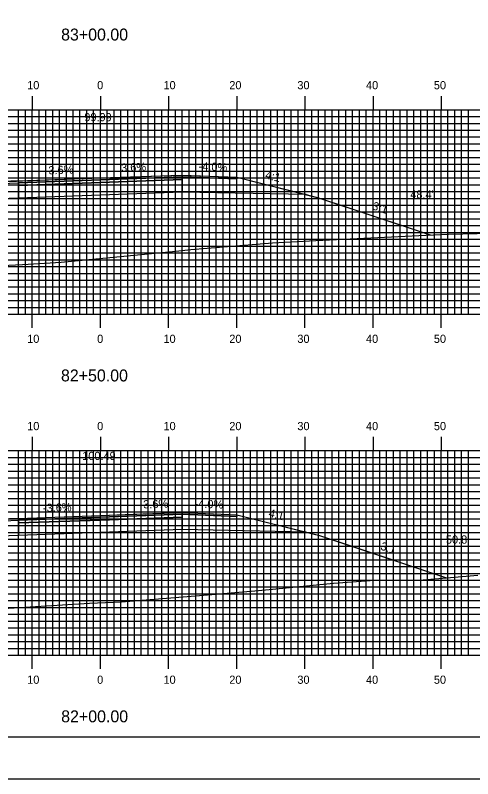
# Model space of a CAD drawing. Extents: x 1762972 to 1763315, y 442591 to 442811.
# Drawn here: x 1763124.8 to 1763191.9, y 442590.5 to 442702.5 of the extents above; entities that cross this region are included whole.
import ezdxf

# ---------------------------------------------------------------- set-up
doc = ezdxf.new("R2010")
doc.units = 0
for name, color, linetype in [('ANNOTATION', 7, 'Continuous'), ('BORDER', 7, 'Continuous'), ('D_Roadway_Centerline', 7, 'Continuous'), ('D_Roadway_Centerline_Text', 7, 'Continuous'), ('D_Roadway_Edge_Shoulder', 7, 'Continuous'), ('D_Roadway_Edge_TW', 7, 'Continuous'), ('D_Roadway_Pavement', 7, 'Continuous'), ('D_Roadway_SlopeLines', 7, 'Continuous'), ('D_Roadway_SubGrade', 7, 'Continuous'), ('D_Text_Standard', 7, 'Continuous'), ('H_V ANNOTATION', 7, 'Continuous'), ('MAJOR', 7, 'Continuous'), ('MINOR', 7, 'Continuous'), ('PLOT BOUNDARY', 7, 'Continuous'), ('S_Roadway_Centerline', 7, 'Continuous')]:
    doc.layers.add(name, color=color, linetype=linetype)

msp = doc.modelspace()

# ---------------------------------------------------------------- linework, layer by layer
at = {"layer": 'BORDER'}
msp.add_lwpolyline([(1762987.69, 442596.67), (1763307.69, 442596.67), (1763307.69, 442806.67), (1762987.69, 442806.67)], close=True, dxfattribs=at)
at = {"layer": 'D_Roadway_Centerline'}
for points in [[(1763079.48, 442666.3), (1763079.48, 442666.3), (1763105.29, 442674.9), (1763105.76, 442675.02), (1763117.29, 442677.9), (1763117.29, 442677.9), (1763117.3, 442677.9), (1763124.95, 442678.21), (1763125.29, 442678.22), (1763125.84, 442678.24), (1763137.29, 442678.66), (1763147.6, 442679.03), (1763149.29, 442679.09), (1763150.49, 442679.04), (1763157.29, 442678.77), (1763157.29, 442678.77), (1763166.47, 442676.47), (1763167.47, 442676.22), (1763169.29, 442675.77), (1763173.61, 442674.33), (1763185.68, 442670.3)], [(1763077.39, 442616.1), (1763105.29, 442625.4), (1763105.29, 442625.4), (1763105.4, 442625.43), (1763105.76, 442625.52), (1763105.76, 442625.52), (1763110.16, 442626.62), (1763117.29, 442628.4), (1763117.29, 442628.4), (1763125.29, 442628.72), (1763137.29, 442629.16), (1763137.29, 442629.16), (1763142.07, 442629.33), (1763149.29, 442629.59), (1763149.3, 442629.59), (1763157.29, 442629.27), (1763167.47, 442626.72), (1763168.66, 442626.42), (1763169.29, 442626.27), (1763169.3, 442626.27), (1763173.13, 442624.99), (1763188.08, 442620.01), (1763188.09, 442620)]]:
    msp.add_lwpolyline(points, dxfattribs=at)
at = {"layer": 'D_Roadway_Edge_Shoulder'}
for points in [[(1763149.29, 442679.09), (1763157.29, 442678.77), (1763157.29, 442678.52), (1763149.29, 442678.84)], [(1763125.29, 442678.22), (1763117.29, 442677.9), (1763117.29, 442677.65), (1763125.29, 442677.97)], [(1763149.29, 442629.59), (1763157.29, 442629.27), (1763157.29, 442629.02), (1763149.29, 442629.34)], [(1763125.29, 442628.72), (1763117.29, 442628.4), (1763117.29, 442628.15), (1763125.29, 442628.47)]]:
    msp.add_lwpolyline(points, close=True, dxfattribs=at)
at = {"layer": 'D_Roadway_Edge_TW'}
for points in [[(1763125.29, 442677.97), (1763125.29, 442678.22), (1763137.29, 442678.66), (1763149.29, 442679.09), (1763149.29, 442678.84), (1763137.29, 442678.41)], [(1763149.29, 442679.09), (1763149.29, 442679.09), (1763149.29, 442678.84), (1763149.29, 442678.84)], [(1763125.29, 442628.47), (1763125.29, 442628.72), (1763137.29, 442629.16), (1763149.29, 442629.59), (1763149.29, 442629.34), (1763137.29, 442628.91)], [(1763149.29, 442629.59), (1763149.29, 442629.59), (1763149.29, 442629.34), (1763149.29, 442629.34)]]:
    msp.add_lwpolyline(points, close=True, dxfattribs=at)
at = {"layer": 'D_Roadway_Pavement'}
for points in [[(1763125.29, 442677.56), (1763125.29, 442677.97), (1763137.29, 442678.41), (1763149.29, 442678.84), (1763149.29, 442678.42), (1763137.29, 442677.99)], [(1763149.29, 442678.84), (1763149.29, 442678.84), (1763149.29, 442678.42), (1763149.29, 442678.42)], [(1763125.29, 442628.06), (1763125.29, 442628.47), (1763137.29, 442628.91), (1763149.29, 442629.34), (1763149.29, 442628.92), (1763137.29, 442628.49)], [(1763149.29, 442629.34), (1763149.29, 442629.34), (1763149.29, 442628.92), (1763149.29, 442628.92)]]:
    msp.add_lwpolyline(points, close=True, dxfattribs=at)
for points in [[(1763149.29, 442678.84), (1763149.29, 442678.42)], [(1763149.29, 442678.84), (1763149.29, 442678.42)], [(1763149.29, 442678.84), (1763149.29, 442678.42)], [(1763149.29, 442629.34), (1763149.29, 442628.92)], [(1763149.29, 442629.34), (1763149.29, 442628.92)], [(1763149.29, 442629.34), (1763149.29, 442628.92)]]:
    msp.add_lwpolyline(points, dxfattribs=at)
at = {"layer": 'D_Roadway_SlopeLines'}
for points in [[(1763157.29, 442678.77), (1763169.29, 442675.77), (1763185.68, 442670.3)], [(1763157.29, 442629.27), (1763169.29, 442626.27), (1763188.09, 442620)]]:
    msp.add_lwpolyline(points, dxfattribs=at)
at = {"layer": 'D_Roadway_SubGrade'}
for points in [[(1763149.29, 442678.42), (1763149.29, 442678.84), (1763157.29, 442678.52), (1763157.29, 442678.77), (1763167.47, 442676.22), (1763149.29, 442676.59)], [(1763117.29, 442677.65), (1763125.29, 442677.97), (1763125.29, 442677.56), (1763125.29, 442675.72), (1763105.76, 442675.02), (1763117.29, 442677.9)], [(1763125.29, 442675.72), (1763125.29, 442677.56), (1763137.29, 442677.99), (1763149.29, 442678.42), (1763149.29, 442676.59), (1763137.29, 442676.16)], [(1763149.29, 442678.42), (1763149.29, 442678.42), (1763149.29, 442676.59), (1763149.29, 442676.59)], [(1763149.29, 442628.92), (1763149.29, 442629.34), (1763157.29, 442629.02), (1763157.29, 442629.27), (1763167.47, 442626.72), (1763149.29, 442627.09)], [(1763117.29, 442628.15), (1763125.29, 442628.47), (1763125.29, 442628.06), (1763125.29, 442626.22), (1763105.76, 442625.52), (1763117.29, 442628.4)], [(1763125.29, 442626.22), (1763125.29, 442628.06), (1763137.29, 442628.49), (1763149.29, 442628.92), (1763149.29, 442627.09), (1763137.29, 442626.66)], [(1763149.29, 442628.92), (1763149.29, 442628.92), (1763149.29, 442627.09), (1763149.29, 442627.09)]]:
    msp.add_lwpolyline(points, close=True, dxfattribs=at)
at = {"layer": 'MAJOR'}
for p, q in [((1763127.29, 442690.67), (1763127.29, 442688.67)), ((1763137.29, 442690.67), (1763137.29, 442688.67)), ((1763147.29, 442690.67), (1763147.29, 442688.67)), ((1763157.29, 442690.67), (1763157.29, 442688.67)), ((1763167.29, 442690.67), (1763167.29, 442688.67)), ((1763177.29, 442690.67), (1763177.29, 442688.67)), ((1763187.29, 442690.67), (1763187.29, 442688.67)), ((1762997.29, 442688.67), (1763277.29, 442688.67)), ((1762997.29, 442688.67), (1763277.29, 442688.67)), ((1763127.29, 442658.67), (1763127.29, 442688.67)), ((1763137.29, 442658.67), (1763137.29, 442688.67)), ((1763147.29, 442658.67), (1763147.29, 442688.67)), ((1763157.29, 442658.67), (1763157.29, 442688.67)), ((1763167.29, 442658.67), (1763167.29, 442688.67)), ((1763177.29, 442658.67), (1763177.29, 442688.67)), ((1763187.29, 442658.67), (1763187.29, 442688.67)), ((1762997.29, 442683.67), (1763277.29, 442683.67)), ((1762997.29, 442678.67), (1763277.29, 442678.67)), ((1762997.29, 442673.67), (1763277.29, 442673.67)), ((1762997.29, 442668.67), (1763277.29, 442668.67)), ((1762997.29, 442663.67), (1763277.29, 442663.67)), ((1762997.29, 442658.67), (1763277.29, 442658.67)), ((1762997.29, 442658.67), (1763277.29, 442658.67)), ((1763127.29, 442656.66), (1763127.29, 442658.67)), ((1763137.29, 442656.66), (1763137.29, 442658.67)), ((1763147.29, 442656.66), (1763147.29, 442658.67)), ((1763157.29, 442656.66), (1763157.29, 442658.67)), ((1763167.29, 442656.66), (1763167.29, 442658.67)), ((1763177.29, 442656.66), (1763177.29, 442658.67)), ((1763187.29, 442656.66), (1763187.29, 442658.67)), ((1763127.29, 442640.67), (1763127.29, 442638.67)), ((1763137.29, 442640.67), (1763137.29, 442638.67)), ((1763147.29, 442640.67), (1763147.29, 442638.67)), ((1763157.29, 442640.67), (1763157.29, 442638.67)), ((1763167.29, 442640.67), (1763167.29, 442638.67)), ((1763177.29, 442640.67), (1763177.29, 442638.67)), ((1763187.29, 442640.67), (1763187.29, 442638.67)), ((1762997.29, 442638.67), (1763277.29, 442638.67)), ((1762997.29, 442638.67), (1763277.29, 442638.67)), ((1763127.29, 442608.67), (1763127.29, 442638.67)), ((1763137.29, 442608.67), (1763137.29, 442638.67)), ((1763147.29, 442608.67), (1763147.29, 442638.67)), ((1763157.29, 442608.67), (1763157.29, 442638.67)), ((1763167.29, 442608.67), (1763167.29, 442638.67)), ((1763177.29, 442608.67), (1763177.29, 442638.67)), ((1763187.29, 442608.67), (1763187.29, 442638.67)), ((1762997.29, 442633.67), (1763277.29, 442633.67)), ((1762997.29, 442628.67), (1763277.29, 442628.67)), ((1762997.29, 442623.67), (1763277.29, 442623.67)), ((1762997.29, 442618.67), (1763277.29, 442618.67)), ((1762997.29, 442613.67), (1763277.29, 442613.67)), ((1762997.29, 442608.67), (1763277.29, 442608.67)), ((1762997.29, 442608.67), (1763277.29, 442608.67)), ((1763127.29, 442606.66), (1763127.29, 442608.67)), ((1763137.29, 442606.66), (1763137.29, 442608.67)), ((1763147.29, 442606.66), (1763147.29, 442608.67)), ((1763157.29, 442606.66), (1763157.29, 442608.67)), ((1763167.29, 442606.66), (1763167.29, 442608.67)), ((1763177.29, 442606.66), (1763177.29, 442608.67)), ((1763187.29, 442606.66), (1763187.29, 442608.67))]:
    msp.add_line(p, q, dxfattribs=at)
at = {"layer": 'MINOR'}
for p, q in [((1763125.29, 442658.67), (1763125.29, 442688.67)), ((1763126.29, 442658.67), (1763126.29, 442688.67)), ((1763128.29, 442658.67), (1763128.29, 442688.67)), ((1763129.29, 442658.67), (1763129.29, 442688.67)), ((1763130.29, 442658.67), (1763130.29, 442688.67)), ((1763131.29, 442658.67), (1763131.29, 442688.67)), ((1763132.29, 442658.67), (1763132.29, 442688.67)), ((1763133.29, 442658.67), (1763133.29, 442688.67)), ((1763134.29, 442658.67), (1763134.29, 442688.67)), ((1763135.29, 442658.67), (1763135.29, 442688.67)), ((1763136.29, 442658.67), (1763136.29, 442688.67)), ((1763138.29, 442658.67), (1763138.29, 442688.67)), ((1763139.29, 442658.67), (1763139.29, 442688.67)), ((1763140.29, 442658.67), (1763140.29, 442688.67)), ((1763141.29, 442658.67), (1763141.29, 442688.67)), ((1763142.29, 442658.67), (1763142.29, 442688.67)), ((1763143.29, 442658.67), (1763143.29, 442688.67)), ((1763144.29, 442658.67), (1763144.29, 442688.67)), ((1763145.29, 442658.67), (1763145.29, 442688.67)), ((1763146.29, 442658.67), (1763146.29, 442688.67)), ((1763148.29, 442658.67), (1763148.29, 442688.67)), ((1763149.29, 442658.67), (1763149.29, 442688.67)), ((1763150.29, 442658.67), (1763150.29, 442688.67)), ((1763151.29, 442658.67), (1763151.29, 442688.67)), ((1763152.29, 442658.67), (1763152.29, 442688.67)), ((1763153.29, 442658.67), (1763153.29, 442688.67)), ((1763154.29, 442658.67), (1763154.29, 442688.67)), ((1763155.29, 442658.67), (1763155.29, 442688.67)), ((1763156.29, 442658.67), (1763156.29, 442688.67)), ((1763158.29, 442658.67), (1763158.29, 442688.67)), ((1763159.29, 442658.67), (1763159.29, 442688.67)), ((1763160.29, 442658.67), (1763160.29, 442688.67)), ((1763161.29, 442658.67), (1763161.29, 442688.67)), ((1763162.29, 442658.67), (1763162.29, 442688.67)), ((1763163.29, 442658.67), (1763163.29, 442688.67)), ((1763164.29, 442658.67), (1763164.29, 442688.67)), ((1763165.29, 442658.67), (1763165.29, 442688.67)), ((1763166.29, 442658.67), (1763166.29, 442688.67)), ((1763168.29, 442658.67), (1763168.29, 442688.67)), ((1763169.29, 442658.67), (1763169.29, 442688.67)), ((1763170.29, 442658.67), (1763170.29, 442688.67)), ((1763171.29, 442658.67), (1763171.29, 442688.67)), ((1763172.29, 442658.67), (1763172.29, 442688.67)), ((1763173.29, 442658.67), (1763173.29, 442688.67)), ((1763174.29, 442658.67), (1763174.29, 442688.67)), ((1763175.29, 442658.67), (1763175.29, 442688.67)), ((1763176.29, 442658.67), (1763176.29, 442688.67)), ((1763178.29, 442658.67), (1763178.29, 442688.67)), ((1763179.29, 442658.67), (1763179.29, 442688.67)), ((1763180.29, 442658.67), (1763180.29, 442688.67)), ((1763181.29, 442658.67), (1763181.29, 442688.67)), ((1763182.29, 442658.67), (1763182.29, 442688.67)), ((1763183.29, 442658.67), (1763183.29, 442688.67)), ((1763184.29, 442658.67), (1763184.29, 442688.67)), ((1763185.29, 442658.67), (1763185.29, 442688.67)), ((1763186.29, 442658.67), (1763186.29, 442688.67)), ((1763188.29, 442658.67), (1763188.29, 442688.67)), ((1763189.29, 442658.67), (1763189.29, 442688.67)), ((1763190.29, 442658.67), (1763190.29, 442688.67)), ((1763191.29, 442658.67), (1763191.29, 442688.67)), ((1762997.29, 442687.67), (1763277.29, 442687.67)), ((1762997.29, 442686.67), (1763277.29, 442686.67)), ((1762997.29, 442685.67), (1763277.29, 442685.67)), ((1762997.29, 442684.67), (1763277.29, 442684.67)), ((1762997.29, 442682.67), (1763277.29, 442682.67)), ((1762997.29, 442681.67), (1763277.29, 442681.67)), ((1762997.29, 442680.67), (1763277.29, 442680.67)), ((1762997.29, 442679.67), (1763277.29, 442679.67)), ((1762997.29, 442677.67), (1763277.29, 442677.67)), ((1762997.29, 442676.67), (1763277.29, 442676.67)), ((1762997.29, 442675.67), (1763277.29, 442675.67)), ((1762997.29, 442674.67), (1763277.29, 442674.67)), ((1762997.29, 442672.67), (1763277.29, 442672.67)), ((1762997.29, 442671.67), (1763277.29, 442671.67)), ((1762997.29, 442670.67), (1763277.29, 442670.67)), ((1762997.29, 442669.67), (1763277.29, 442669.67)), ((1762997.29, 442667.67), (1763277.29, 442667.67)), ((1762997.29, 442666.67), (1763277.29, 442666.67)), ((1762997.29, 442665.67), (1763277.29, 442665.67)), ((1762997.29, 442664.67), (1763277.29, 442664.67)), ((1762997.29, 442662.67), (1763277.29, 442662.67)), ((1762997.29, 442661.67), (1763277.29, 442661.67)), ((1762997.29, 442660.67), (1763277.29, 442660.67)), ((1762997.29, 442659.67), (1763277.29, 442659.67)), ((1763125.29, 442608.67), (1763125.29, 442638.67)), ((1763126.29, 442608.67), (1763126.29, 442638.67)), ((1763128.29, 442608.67), (1763128.29, 442638.67)), ((1763129.29, 442608.67), (1763129.29, 442638.67)), ((1763130.29, 442608.67), (1763130.29, 442638.67)), ((1763131.29, 442608.67), (1763131.29, 442638.67)), ((1763132.29, 442608.67), (1763132.29, 442638.67)), ((1763133.29, 442608.67), (1763133.29, 442638.67)), ((1763134.29, 442608.67), (1763134.29, 442638.67)), ((1763135.29, 442608.67), (1763135.29, 442638.67)), ((1763136.29, 442608.67), (1763136.29, 442638.67)), ((1763138.29, 442608.67), (1763138.29, 442638.67)), ((1763139.29, 442608.67), (1763139.29, 442638.67)), ((1763140.29, 442608.67), (1763140.29, 442638.67)), ((1763141.29, 442608.67), (1763141.29, 442638.67)), ((1763142.29, 442608.67), (1763142.29, 442638.67)), ((1763143.29, 442608.67), (1763143.29, 442638.67)), ((1763144.29, 442608.67), (1763144.29, 442638.67)), ((1763145.29, 442608.67), (1763145.29, 442638.67)), ((1763146.29, 442608.67), (1763146.29, 442638.67)), ((1763148.29, 442608.67), (1763148.29, 442638.67)), ((1763149.29, 442608.67), (1763149.29, 442638.67)), ((1763150.29, 442608.67), (1763150.29, 442638.67)), ((1763151.29, 442608.67), (1763151.29, 442638.67)), ((1763152.29, 442608.67), (1763152.29, 442638.67)), ((1763153.29, 442608.67), (1763153.29, 442638.67)), ((1763154.29, 442608.67), (1763154.29, 442638.67)), ((1763155.29, 442608.67), (1763155.29, 442638.67)), ((1763156.29, 442608.67), (1763156.29, 442638.67)), ((1763158.29, 442608.67), (1763158.29, 442638.67)), ((1763159.29, 442608.67), (1763159.29, 442638.67)), ((1763160.29, 442608.67), (1763160.29, 442638.67)), ((1763161.29, 442608.67), (1763161.29, 442638.67)), ((1763162.29, 442608.67), (1763162.29, 442638.67)), ((1763163.29, 442608.67), (1763163.29, 442638.67)), ((1763164.29, 442608.67), (1763164.29, 442638.67)), ((1763165.29, 442608.67), (1763165.29, 442638.67)), ((1763166.29, 442608.67), (1763166.29, 442638.67)), ((1763168.29, 442608.67), (1763168.29, 442638.67)), ((1763169.29, 442608.67), (1763169.29, 442638.67)), ((1763170.29, 442608.67), (1763170.29, 442638.67)), ((1763171.29, 442608.67), (1763171.29, 442638.67)), ((1763172.29, 442608.67), (1763172.29, 442638.67)), ((1763173.29, 442608.67), (1763173.29, 442638.67)), ((1763174.29, 442608.67), (1763174.29, 442638.67)), ((1763175.29, 442608.67), (1763175.29, 442638.67)), ((1763176.29, 442608.67), (1763176.29, 442638.67)), ((1763178.29, 442608.67), (1763178.29, 442638.67)), ((1763179.29, 442608.67), (1763179.29, 442638.67)), ((1763180.29, 442608.67), (1763180.29, 442638.67)), ((1763181.29, 442608.67), (1763181.29, 442638.67)), ((1763182.29, 442608.67), (1763182.29, 442638.67)), ((1763183.29, 442608.67), (1763183.29, 442638.67)), ((1763184.29, 442608.67), (1763184.29, 442638.67)), ((1763185.29, 442608.67), (1763185.29, 442638.67)), ((1763186.29, 442608.67), (1763186.29, 442638.67)), ((1763188.29, 442608.67), (1763188.29, 442638.67)), ((1763189.29, 442608.67), (1763189.29, 442638.67)), ((1763190.29, 442608.67), (1763190.29, 442638.67)), ((1763191.29, 442608.67), (1763191.29, 442638.67)), ((1762997.29, 442637.67), (1763277.29, 442637.67)), ((1762997.29, 442636.67), (1763277.29, 442636.67)), ((1762997.29, 442635.67), (1763277.29, 442635.67)), ((1762997.29, 442634.67), (1763277.29, 442634.67)), ((1762997.29, 442632.67), (1763277.29, 442632.67)), ((1762997.29, 442631.67), (1763277.29, 442631.67)), ((1762997.29, 442630.67), (1763277.29, 442630.67)), ((1762997.29, 442629.67), (1763277.29, 442629.67)), ((1762997.29, 442627.67), (1763277.29, 442627.67)), ((1762997.29, 442626.67), (1763277.29, 442626.67)), ((1762997.29, 442625.67), (1763277.29, 442625.67)), ((1762997.29, 442624.67), (1763277.29, 442624.67)), ((1762997.29, 442622.67), (1763277.29, 442622.67)), ((1762997.29, 442621.67), (1763277.29, 442621.67)), ((1762997.29, 442620.67), (1763277.29, 442620.67)), ((1762997.29, 442619.67), (1763277.29, 442619.67)), ((1762997.29, 442617.67), (1763277.29, 442617.67)), ((1762997.29, 442616.67), (1763277.29, 442616.67)), ((1762997.29, 442615.67), (1763277.29, 442615.67)), ((1762997.29, 442614.67), (1763277.29, 442614.67)), ((1762997.29, 442612.67), (1763277.29, 442612.67)), ((1762997.29, 442611.67), (1763277.29, 442611.67)), ((1762997.29, 442610.67), (1763277.29, 442610.67)), ((1762997.29, 442609.67), (1763277.29, 442609.67))]:
    msp.add_line(p, q, dxfattribs=at)
at = {"layer": 'PLOT BOUNDARY'}
msp.add_lwpolyline([(1762971.51, 442590.55), (1763311.51, 442590.55), (1763311.51, 442810.55), (1762971.51, 442810.55)], close=True, dxfattribs=at)
at = {"layer": 'S_Roadway_Centerline'}
for points in [[(1762997.29, 442665.43), (1763013.11, 442665.98), (1763021.07, 442666.09), (1763036.04, 442666.99), (1763038.16, 442667.04), (1763040.53, 442666.99), (1763044.59, 442666.73), (1763052.77, 442665.87), (1763057.54, 442666.14), (1763064.98, 442666.52), (1763076.16, 442666.41), (1763077.6, 442666.34), (1763080.19, 442666.28), (1763113.21, 442665.36), (1763114.75, 442665.44), (1763125.83, 442665.97), (1763131.53, 442666.32), (1763148.37, 442667.91), (1763150.54, 442668.16), (1763162.56, 442669.17), (1763168.92, 442669.48), (1763185.04, 442670.28), (1763188.37, 442670.4), (1763198.83, 442670.65)], [(1763074.61, 442616.05), (1763085.57, 442616.27), (1763087.55, 442616.24), (1763091.19, 442616), (1763099.37, 442615.12), (1763102.82, 442615.01), (1763115.53, 442614.78), (1763121.4, 442615.41), (1763135.67, 442616.3), (1763140.38, 442616.47), (1763154.21, 442617.61), (1763158.15, 442617.94), (1763159.41, 442618.06), (1763162.05, 442618.31), (1763171.51, 442619.25), (1763177.55, 442619.67), (1763184.04, 442619.67), (1763192.69, 442620.38)]]:
    msp.add_lwpolyline(points, dxfattribs=at)

# ---------------------------------------------------------------- texts
at = {"layer": 'ANNOTATION'}
for s, rotation, p in [('3.6%', 2.0618, (1763140.35, 442679.57)), ('-4.0%', 357.7093, (1763151.68, 442679.79)), ('-3.6%', 2.0617, (1763129.15, 442679.16)), ('4:1', 345.9607, (1763161.39, 442678.6)), ('3:1', 341.5633, (1763177.09, 442674.08)), ('3.6%', 2.0617, (1763143.59, 442630.18)), ('-4.0%', 357.7096, (1763151.09, 442630.32)), ('-3.6%', 2.0618, (1763128.88, 442629.65)), ('4:1', 345.9606, (1763161.89, 442628.98)), ('3:1', 341.5642, (1763178.29, 442624.18))]:
    msp.add_text(s, height=1.2, rotation=rotation, dxfattribs=at).set_placement(p)
at = {"layer": 'D_Roadway_Centerline'}
for s, p in [('C', (1763137.29, 442678.66)), ('L', (1763137.29, 442678.65)), ('C', (1763137.29, 442629.16)), ('L', (1763137.29, 442629.15))]:
    msp.add_text(s, height=0.0146, dxfattribs=at).set_placement(p)
at = {"layer": 'D_Roadway_Centerline_Text'}
for s, p in [('99.99', (1763134.93, 442686.98)), ('100.49', (1763134.62, 442637.3))]:
    msp.add_text(s, height=1.2, dxfattribs=at).set_placement(p)
at = {"layer": 'D_Text_Standard'}
for s, p in [("48.4'", (1763182.76, 442675.65)), ("50.8'", (1763187.99, 442625.03))]:
    msp.add_text(s, height=1.2, dxfattribs=at).set_placement(p)
at = {"layer": 'H_V ANNOTATION'}
for s, height, p in [('83+00.00', 1.75, (1763131.52, 442698.82)), ('10', 1.2, (1763126.54, 442691.67)), ('0', 1.2, (1763136.81, 442691.67)), ('10', 1.2, (1763146.54, 442691.67)), ('20', 1.2, (1763156.2, 442691.67)), ('30', 1.2, (1763166.19, 442691.67)), ('40', 1.2, (1763176.26, 442691.67)), ('50', 1.2, (1763186.22, 442691.67)), ('10', 1.2, (1763126.54, 442654.47)), ('0', 1.2, (1763136.81, 442654.47)), ('10', 1.2, (1763146.54, 442654.47)), ('20', 1.2, (1763156.2, 442654.47)), ('30', 1.2, (1763166.19, 442654.47)), ('40', 1.2, (1763176.26, 442654.47)), ('50', 1.2, (1763186.22, 442654.47)), ('82+50.00', 1.75, (1763131.5, 442648.82)), ('10', 1.2, (1763126.54, 442641.67)), ('0', 1.2, (1763136.81, 442641.67)), ('10', 1.2, (1763146.54, 442641.67)), ('20', 1.2, (1763156.2, 442641.67)), ('30', 1.2, (1763166.19, 442641.67)), ('40', 1.2, (1763176.26, 442641.67)), ('50', 1.2, (1763186.22, 442641.67)), ('10', 1.2, (1763126.54, 442604.47)), ('0', 1.2, (1763136.81, 442604.47)), ('10', 1.2, (1763146.54, 442604.47)), ('20', 1.2, (1763156.2, 442604.47)), ('30', 1.2, (1763166.19, 442604.47)), ('40', 1.2, (1763176.26, 442604.47)), ('50', 1.2, (1763186.22, 442604.47)), ('82+00.00', 1.75, (1763131.53, 442598.82))]:
    msp.add_text(s, height=height, dxfattribs=at).set_placement(p)

doc.saveas('drawing.dxf')
